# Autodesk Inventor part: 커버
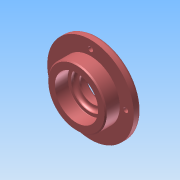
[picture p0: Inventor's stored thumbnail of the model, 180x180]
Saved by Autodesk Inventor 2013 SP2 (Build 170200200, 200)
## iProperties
Created: 2026-07
Part Number: 커버
Material: Generic
Document SubType Name: Modeling
Designer: aa
Density: 1 g/cm^3
Author: aa
변환 표준: STEP AP214IS
전처리기: Build: 200, Release: 2013 SP2 Update 6 - Date: Thu 07/17/2014
전송 단위: 밀리미터
불확실성: 0.01
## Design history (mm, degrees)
node "커버1"
node "솔리드1"
node "기준1"
